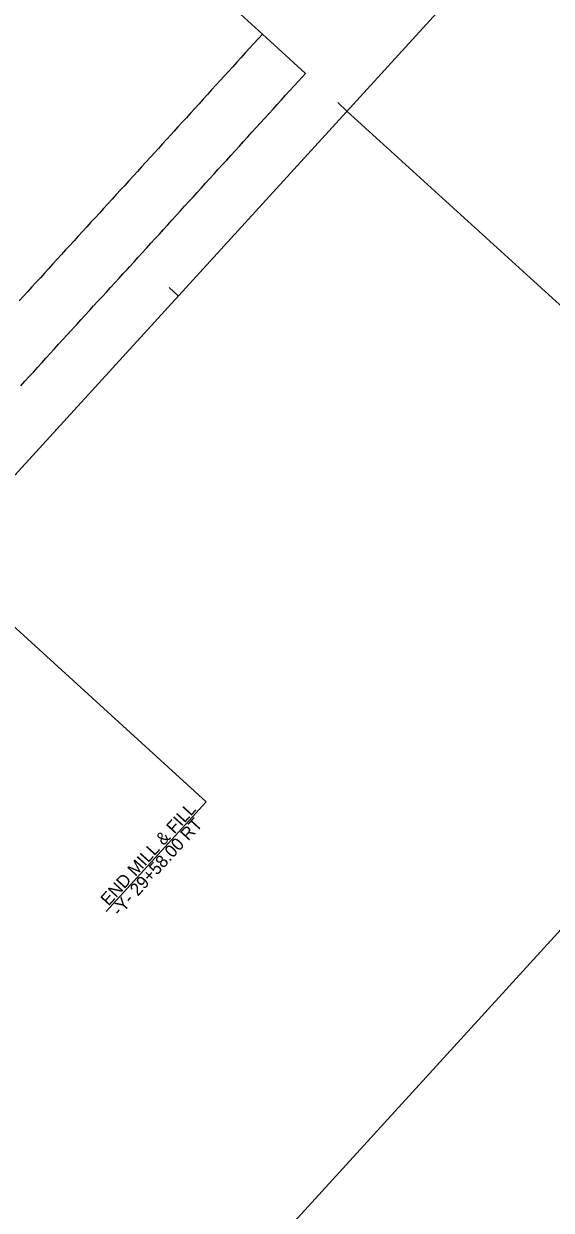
# Model space of a CAD drawing. Extents: x 1807040 to 1808827, y 913493 to 915218.
# Drawn here: x 1808009.9 to 1808220.6, y 913761.8 to 914236.2 of the extents above; entities that cross this region are included whole.
import ezdxf

# ---------------------------------------------------------------- set-up
doc = ezdxf.new("R2010")
doc.units = 0
for name, color, linetype in [('Prop Dimension', 7, 'Continuous'), ('Prop EOT', 7, 'Continuous'), ('Prop Horizontal Alignment Station Label', 7, 'Continuous'), ('Prop Horizontal Alignment Tick Small', 7, 'Continuous'), ('Scratch_Level_0', 7, 'Continuous'), ('Scratch_Level_1', 7, 'Continuous'), ('Scratch_Level_3', 7, 'Continuous')]:
    doc.layers.add(name, color=color, linetype=linetype)

msp = doc.modelspace()

# ---------------------------------------------------------------- linework, layer by layer
at = {"layer": 'Prop Dimension'}
for p, q in [((1808105.21, 914232.08), (1808010.39, 914318.51)), ((1808082.8, 913925.07), (1808009.86, 913991.55)), ((1808042.82, 913881.21), (1808082.8, 913925.07))]:
    msp.add_line(p, q, dxfattribs=at)
at = {"layer": 'Prop EOT'}
for p, q in [((1808122.43, 914216.38), (1808105.21, 914232.08)), ((1808009.86, 913991.55), (1807992.66, 914007.23))]:
    msp.add_line(p, q, dxfattribs=at)
for points in [[(1808105.21, 914232.08), (1808103.55, 914230.26), (1808101.87, 914228.41), (1808101.74, 914228.27), (1808100.06, 914226.42), (1808098.38, 914224.57), (1808096.7, 914222.72), (1808095.02, 914220.87), (1808093.34, 914219.02), (1808091.65, 914217.17), (1808089.97, 914215.32), (1808088.29, 914213.47), (1808086.61, 914211.62), (1808084.93, 914209.76), (1808083.25, 914207.91), (1808081.57, 914206.06), (1808079.89, 914204.21), (1808078.21, 914202.36), (1808076.52, 914200.51), (1808074.84, 914198.66), (1808073.16, 914196.81), (1808071.48, 914194.96), (1808069.8, 914193.11), (1808068.72, 914191.93), (1808067.04, 914190.08), (1808065.35, 914188.23), (1808063.67, 914186.39), (1808061.98, 914184.54), (1808060.3, 914182.69), (1808058.61, 914180.85), (1808056.93, 914179), (1808055.24, 914177.15), (1808053.56, 914175.31), (1808051.87, 914173.46), (1808050.19, 914171.61), (1808048.5, 914169.77), (1808046.82, 914167.92), (1808045.13, 914166.07), (1808043.45, 914164.22), (1808041.76, 914162.38), (1808040.08, 914160.53), (1808038.39, 914158.68), (1808036.71, 914156.84), (1808035.02, 914154.99), (1808033.34, 914153.14), (1808031.65, 914151.3), (1808029.97, 914149.45), (1808028.28, 914147.6), (1808026.6, 914145.76), (1808024.91, 914143.91), (1808023.23, 914142.06), (1808021.54, 914140.22), (1808019.86, 914138.37), (1808018.17, 914136.52), (1808016.49, 914134.68), (1808014.8, 914132.83), (1808013.12, 914130.98), (1808011.43, 914129.13), (1808009.75, 914127.29)], [(1808008.65, 914091.42), (1808010.33, 914093.27), (1808012.01, 914095.12), (1808013.69, 914096.97), (1808015.37, 914098.82), (1808017.06, 914100.67), (1808018.74, 914102.52), (1808020.42, 914104.37), (1808022.1, 914106.22), (1808023.79, 914108.07), (1808025.47, 914109.92), (1808027.15, 914111.77), (1808028.83, 914113.61), (1808030.52, 914115.46), (1808031.04, 914116.03), (1808032.72, 914117.88), (1808034.41, 914119.72), (1808036.1, 914121.56), (1808037.79, 914123.41), (1808039.48, 914125.25), (1808041.17, 914127.09), (1808042.86, 914128.93), (1808044.55, 914130.78), (1808046.24, 914132.62), (1808047.93, 914134.46), (1808049.62, 914136.31), (1808051.3, 914138.15), (1808052.26, 914139.2), (1808053.94, 914141.05), (1808055.63, 914142.9), (1808057.31, 914144.75), (1808058.99, 914146.6), (1808060.67, 914148.45), (1808062.35, 914150.3), (1808064.03, 914152.14), (1808065.72, 914153.99), (1808067.4, 914155.84), (1808069.08, 914157.69), (1808070.76, 914159.54), (1808072.44, 914161.39), (1808074.12, 914163.24), (1808075.81, 914165.09), (1808077.49, 914166.94), (1808079.17, 914168.79), (1808080.85, 914170.64), (1808082.53, 914172.49), (1808084.21, 914174.34), (1808085.9, 914176.19), (1808087.58, 914178.04), (1808089.26, 914179.89), (1808090.94, 914181.74), (1808092.62, 914183.59), (1808094.3, 914185.44), (1808095.99, 914187.29), (1808097.67, 914189.14), (1808099.35, 914190.99), (1808101.03, 914192.84), (1808102.71, 914194.69), (1808104.39, 914196.54), (1808106.08, 914198.39), (1808107.76, 914200.24), (1808109.44, 914202.09), (1808111.12, 914203.94), (1808112.8, 914205.79), (1808114.48, 914207.64), (1808116.16, 914209.49), (1808117.85, 914211.34), (1808119.53, 914213.19), (1808121.21, 914215.04), (1808122.43, 914216.38)]]:
    msp.add_lwpolyline(points, dxfattribs=at)
at = {"layer": 'Prop Horizontal Alignment Station Label'}
msp.add_line((1808240.7, 914108.59), (1808138.97, 914201.31), dxfattribs=at)
at = {"layer": 'Prop Horizontal Alignment Tick Small'}
for p, q in [((1808138.97, 914201.31), (1808135.28, 914204.67)), ((1808071.61, 914127.4), (1808067.92, 914130.77))]:
    msp.add_line(p, q, dxfattribs=at)
at = {"layer": 'Scratch_Level_0'}
for p, q in [((1808101.74, 914228.27), (1808100.06, 914226.42)), ((1808101.87, 914228.41), (1808101.74, 914228.27)), ((1808103.55, 914230.26), (1808101.87, 914228.41)), ((1808105.21, 914232.08), (1808103.55, 914230.26)), ((1808122.43, 914216.38), (1808105.21, 914232.08)), ((1808100.06, 914226.42), (1808098.38, 914224.57)), ((1808121.21, 914215.04), (1808122.43, 914216.38)), ((1808116.16, 914209.49), (1808117.85, 914211.34)), ((1808081.57, 914206.06), (1808079.89, 914204.21)), ((1808071.48, 914194.96), (1808069.8, 914193.11)), ((1808101.03, 914192.84), (1808102.71, 914194.69)), ((1808102.71, 914194.69), (1808104.39, 914196.54)), ((1808067.04, 914190.08), (1808065.35, 914188.23)), ((1808099.35, 914190.99), (1808101.03, 914192.84)), ((1808092.62, 914183.59), (1808094.3, 914185.44)), ((1808094.3, 914185.44), (1808095.99, 914187.29)), ((1808058.61, 914180.85), (1808056.93, 914179)), ((1808060.3, 914182.69), (1808058.61, 914180.85)), ((1808061.98, 914184.54), (1808060.3, 914182.69)), ((1808089.26, 914179.89), (1808090.94, 914181.74)), ((1808090.94, 914181.74), (1808092.62, 914183.59)), ((1808056.93, 914179), (1808055.24, 914177.15)), ((1808038.39, 914158.68), (1808036.71, 914156.84)), ((1808067.4, 914155.84), (1808069.08, 914157.69)), ((1808069.08, 914157.69), (1808070.76, 914159.54)), ((1808026.6, 914145.76), (1808024.91, 914143.91)), ((1808052.26, 914139.2), (1808053.94, 914141.05)), ((1808014.8, 914132.83), (1808013.12, 914130.98)), ((1808013.12, 914130.98), (1808011.43, 914129.13)), ((1808036.1, 914121.56), (1808037.79, 914123.41)), ((1808032.72, 914117.88), (1808034.41, 914119.72)), ((1808034.41, 914119.72), (1808036.1, 914121.56)), ((1808031.04, 914116.03), (1808032.72, 914117.88)), ((1808018.74, 914102.52), (1808020.42, 914104.37)), ((1808020.42, 914104.37), (1808022.1, 914106.22)), ((1808022.1, 914106.22), (1808022.7, 914106.87)), ((1808015.37, 914098.82), (1808017.06, 914100.67)), ((1808017.06, 914100.67), (1808018.74, 914102.52)), ((1808013.69, 914096.97), (1808015.37, 914098.82))]:
    msp.add_line(p, q, dxfattribs=at)
for points in [[(1808098.38, 914224.57), (1808096.7, 914222.72), (1808095.02, 914220.87)], [(1808095.02, 914220.87), (1808093.34, 914219.02), (1808091.65, 914217.17), (1808089.97, 914215.32), (1808088.29, 914213.47), (1808086.61, 914211.62), (1808084.93, 914209.76), (1808083.25, 914207.91), (1808081.57, 914206.06)], [(1808117.85, 914211.34), (1808119.53, 914213.19), (1808121.21, 914215.04)], [(1808104.39, 914196.54), (1808106.08, 914198.39), (1808107.76, 914200.24), (1808109.44, 914202.09), (1808111.12, 914203.94), (1808112.8, 914205.79), (1808114.48, 914207.64), (1808116.16, 914209.49)], [(1808079.89, 914204.21), (1808078.21, 914202.36), (1808076.52, 914200.51), (1808074.84, 914198.66)], [(1808074.84, 914198.66), (1808073.16, 914196.81), (1808071.48, 914194.96)], [(1808069.8, 914193.11), (1808068.72, 914191.93), (1808067.04, 914190.08)], [(1808095.99, 914187.29), (1808097.67, 914189.14), (1808099.35, 914190.99)], [(1808065.35, 914188.23), (1808063.67, 914186.39), (1808061.98, 914184.54)], [(1808055.24, 914177.15), (1808053.56, 914175.31), (1808051.87, 914173.46), (1808050.19, 914171.61)], [(1808079.17, 914168.79), (1808080.85, 914170.64), (1808082.53, 914172.49), (1808084.21, 914174.34), (1808085.9, 914176.19)], [(1808085.9, 914176.19), (1808087.58, 914178.04), (1808089.26, 914179.89)], [(1808050.19, 914171.61), (1808048.5, 914169.77), (1808046.82, 914167.92), (1808045.13, 914166.07)], [(1808045.13, 914166.07), (1808043.45, 914164.22), (1808041.76, 914162.38), (1808040.08, 914160.53), (1808038.39, 914158.68)], [(1808075.81, 914165.09), (1808077.49, 914166.94), (1808079.17, 914168.79)], [(1808070.76, 914159.54), (1808072.44, 914161.39), (1808074.12, 914163.24), (1808075.81, 914165.09)], [(1808036.71, 914156.84), (1808035.02, 914154.99), (1808033.34, 914153.14), (1808031.65, 914151.3), (1808029.97, 914149.45)], [(1808060.67, 914148.45), (1808062.35, 914150.3), (1808064.03, 914152.14), (1808065.72, 914153.99), (1808067.4, 914155.84)], [(1808029.97, 914149.45), (1808028.28, 914147.6), (1808026.6, 914145.76)], [(1808057.31, 914144.75), (1808058.99, 914146.6), (1808060.67, 914148.45)], [(1808024.91, 914143.91), (1808023.23, 914142.06), (1808021.54, 914140.22)], [(1808053.94, 914141.05), (1808055.63, 914142.9), (1808057.31, 914144.75)], [(1808021.54, 914140.22), (1808019.86, 914138.37), (1808018.17, 914136.52)], [(1808042.86, 914128.93), (1808044.55, 914130.78), (1808046.24, 914132.62), (1808047.93, 914134.46), (1808049.62, 914136.31), (1808051.3, 914138.15), (1808052.26, 914139.2)], [(1808018.17, 914136.52), (1808016.49, 914134.68), (1808014.8, 914132.83)], [(1808011.43, 914129.13), (1808009.75, 914127.29), (1808008.06, 914125.44)], [(1808037.79, 914123.41), (1808039.48, 914125.25), (1808041.17, 914127.09), (1808042.86, 914128.93)], [(1808025.47, 914109.92), (1808027.15, 914111.77), (1808028.83, 914113.61), (1808030.52, 914115.46), (1808031.04, 914116.03)], [(1808022.7, 914106.87), (1808023.79, 914108.07), (1808025.47, 914109.92)], [(1808008.65, 914091.42), (1808010.33, 914093.27), (1808012.01, 914095.12), (1808013.69, 914096.97)]]:
    msp.add_lwpolyline(points, dxfattribs=at)
at = {"layer": 'Scratch_Level_1'}
msp.add_lwpolyline([(1807489.01, 913846.57), (1807877.03, 913492.93), (1808826.79, 914534.98), (1808438.77, 914888.63)], close=True, dxfattribs=at)
at = {"layer": 'Scratch_Level_3'}
msp.add_line((1807667.44, 913683.95), (1808610.51, 914718.66), dxfattribs=at)

# ---------------------------------------------------------------- texts
at = {"layer": 'Prop Dimension'}
for s, p in [('END MILL & FILL', (1808043.74, 913883.19)), ('-Y- 29+58.00 RT', (1808048.18, 913879.15))]:
    msp.add_text(s, height=5, rotation=47.6532, dxfattribs=at).set_placement(p)

doc.saveas('drawing.dxf')
